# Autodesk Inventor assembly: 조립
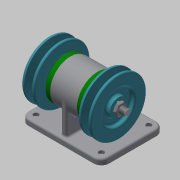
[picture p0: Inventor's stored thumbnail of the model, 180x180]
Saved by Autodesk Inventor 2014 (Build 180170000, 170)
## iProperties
Created: 2019-09
Part Number: 조립
Document SubType Name: Assembly
Designer: kh
Author: kh
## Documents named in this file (10)
- C:\Users\kh\Desktop\490904V1016\조립.iam
- C:\Users\kh\Desktop\490904V1016\본체.ipt
- C:\Users\kh\Desktop\490904V1016\V-벨트풀리.ipt
- C:\Users\kh\Desktop\490904V1016\너트 M10x1.ipt
- C:\Users\kh\Desktop\490904V1016\베어링 6004.ipt
- C:\Users\kh\Desktop\490904V1016\볼트 M4.ipt
- C:\Users\kh\Desktop\490904V1016\오일 실 17 30 5.ipt
- C:\Users\kh\Desktop\490904V1016\축.ipt
- C:\Users\kh\Desktop\490904V1016\커버.ipt
- C:\Users\kh\Desktop\490904V1016\키 5 x 5 x 12.ipt
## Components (2 placed, 1 different names)
1. V-벨트풀리:1 — Insert:16, Mate:1, Insert:17
2. V-벨트풀리:2 — Insert:18, Mate:2, Insert:19
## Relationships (6: Insert 4, Mate 2)
- Insert:16: V-벨트풀리:1
- Mate:1: V-벨트풀리:1
- Insert:17: V-벨트풀리:1
- Insert:18: V-벨트풀리:2
- Mate:2: V-벨트풀리:2
- Insert:19: V-벨트풀리:2
